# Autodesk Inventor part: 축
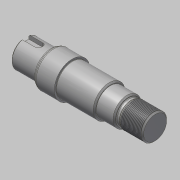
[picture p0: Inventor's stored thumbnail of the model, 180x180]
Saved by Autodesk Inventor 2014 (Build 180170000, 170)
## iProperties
Created: 2019-05
Part Number: 축
Material: 강철, 연강
Document SubType Name: Modeling
Designer: mduedu
Density: 1 g/cm^3
Appearance: Steel
Author: mduedu
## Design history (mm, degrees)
sketch "스케치1"
  geometry: L1 (0, 0)-(20, 0); L2 (20, 0)-(20, 11); L3 (20, 11)-(0, 11); L4 (0, 11)-(0, 0); L5 (20, 0)-(37, 0); L6 (37, 0)-(37, 14); L7 (37, 14)-(20, 14); L8 (20, 14)-(20, 0); L9 (37, 0)-(67, 0); L10 (67, 0)-(67, 12.5); L11 (67, 12.5)-(37, 12.5); L12 (37, 12.5)-(37, 0); L13 (67, 0)-(81, 0); L14 (81, 0)-(81, 11); L15 (81, 11)-(67, 11); L16 (67, 11)-(67, 0); L17 (81, 0)-(102, 0); L18 (102, 0)-(102, 10); L19 (102, 10)-(81, 10); L20 (81, 10)-(81, 0)
  constraints: 40 end point, 10 parallel, 5 horizontal, 5 perpendicular
  dimensions: "d0" = 102 distance between parallel lines of L18 L4; "d2" = 21 distance of L18.end L19.end; "d3" = 14 distance of L14.end L15.end; "d4" = 30 distance of L10.end L11.end; "d5" = 17 distance of L6.end L7.end; "d6" = 22 diameter of L3 L1; "d7" = 28 diameter of L7 L5; "d8" = 25 diameter of L11 L9; "d9" = 22 diameter of L15 L13; "d10" = 20 diameter of L19 L17
revolve "회전1" sketch "스케치1" stored, may be unused: angle "d11" = 90 deg
chamfer "모따기1" distance "d12" = 2.34; stored, may be unused: second distance "d13" = 2, angle "d14" = 30 deg
fillet "모깎기1" dims "d15" = 2, "d16" = 1
fillet "모깎기2" dims "d17" = 0.3
chamfer "모따기2" distance "d18" = 1; stored, may be unused: second distance "d19" = 2, angle "d20" = 30 deg
sketch "스케치2"
  geometry: L1 (102, -10)-(81, -10) reference; L2 (81, -10)-(81, -11) reference; L3 (81, -11)-(67, -11) reference; L4 (67, -11)-(67, -11.5) reference; L5 (67, -11.5)-(66, -12.5) reference; L6 (66, -12.5)-(37.3, -12.5) reference; L7 (37, -12.8)-(37, -14) reference; L8 (37, -14)-(22.876, -14) reference; L9 (21.876, -13.732)-(20.5, -12.938) reference; L10 (20, -12.072)-(20, -11) reference; L11 (20, -11)-(0, -11) reference; L12 (0, -11)-(0, 11) reference; L13 (0, 11)-(20, 11) reference; L14 (20, 11)-(20, 12.072) reference; L15 (20.5, 12.938)-(21.876, 13.732) reference; L16 (22.876, 14)-(37, 14) reference; L17 (37, 14)-(37, 12.8) reference; L18 (37.3, 12.5)-(66, 12.5) reference; L19 (66, 12.5)-(67, 11.5) reference; L20 (67, 11.5)-(67, 11) reference; L21 (67, 11)-(81, 11) reference; L22 (81, 11)-(81, 10) reference; L23 (81, 10)-(102, 10) reference; L24 (102, 10)-(102, -10) reference; L25 (0, 0)-(102, 0); L26 (81, 10)-(84.726, 10); L27 (83.34, 9.2)-(81, 9.2); L28 (81, 9.2)-(81, 10); L29 (84.726, 10)-(83.34, 9.2); A1 r 0.3 centre (37.3, -12.8) between (37.3, -12.5) and (37, -12.8) reference; A2 r 2 centre (22.876, -12) between (21.876, -13.732) and (22.876, -14) reference; A3 r 1 centre (21, -12.072) between (20, -12.072) and (20.5, -12.938) reference; A4 r 1 centre (21, 12.072) between (20.5, 12.938) and (20, 12.072) reference; A5 r 2 centre (22.876, 12) between (22.876, 14) and (21.876, 13.732) reference; A6 r 0.3 centre (37.3, 12.8) between (37, 12.8) and (37.3, 12.5) reference
  constraints: 10 end point, 1 horizontal, 1 midpoint, 1 parallel, 1 vertical
  dimensions: "d21" = 18.4 diameter of L27 L25; "d23" = 2.34 distance of L27.start L27.end; "d24" = 30 deg angle of L23 L29
revolve "회전2" sketch "스케치2" stored, may be unused: angle "d25" = 90 deg
fillet "모깎기3" dims "d26" = 0.6
chamfer "모따기3" distance "d27" = 1; stored, may be unused: second distance "d28" = 2, angle "d29" = 30 deg
feature "스레드1" dims "d30" = 10, "d31" = 0
chamfer "모따기4" distance "d32" = 1; stored, may be unused: second distance "d33" = 2, angle "d34" = 30 deg
node "작업 평면1"
sketch "스케치3"
  geometry: L1 (10, -3)-(-1, -3); L2 (-1, -3)-(-1, 3); L3 (-1, 3)-(10, 3); L4 (10, 3)-(10, -3); 3 further points
  constraints: 8 end point, 2 midpoint, 2 parallel, 1 coincident, 1 horizontal, 1 perpendicular, 1 vertical alignment, 2 other
  dimensions: "d35" = 14 dimension on L4; "d37" = 6 distance between parallel lines of L3 L1
extrude "돌출1" cut sketch "스케치3" distance "d38" = 3.5; taper "d39" = 0 deg
chamfer "모따기5" distance "d40" = 1; stored, may be unused: second distance "d41" = 2, angle "d42" = 30 deg
node "솔리드1"
node "절단 모서리 투영1"
